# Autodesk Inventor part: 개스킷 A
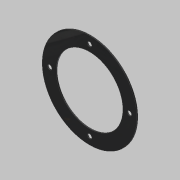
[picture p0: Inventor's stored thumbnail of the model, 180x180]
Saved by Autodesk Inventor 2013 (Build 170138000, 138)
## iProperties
Created: 2019-10
Part Number: 개스킷 A
Material: 고무
Document SubType Name: Modeling
Designer: mduedu
Density: 1 g/cm^3
Author: mduedu
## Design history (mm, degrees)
sketch "스케치1"
  geometry: C1 r 47.5 at (0, 0); C2 r 33.5 at (0, 0); 1 further point
  constraints: 2 centre point, 2 coincident
  dimensions: "d0" = 95 diameter of C1; "d1" = 67 diameter of C2
extrude "돌출1" new body sketch "스케치1" distance "d2" = 1; taper "d3" = 0 deg
sketch "스케치2" dims "d4" = 80
  geometry: C1 r 2.25 at (0, 40); 2 further points
  constraints: 2 vertical alignment, 1 centre point, 1 coincident, 2 other
  dimensions: "d5" = 4.5 diameter of C1
extrude "돌출2" cut sketch "스케치2" stored distance "d6" = 1; taper "d7" = 0 deg
node "솔리드1"
pattern_circular "원형 패턴1" dims angle "d9" = 360 deg
